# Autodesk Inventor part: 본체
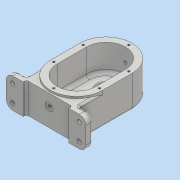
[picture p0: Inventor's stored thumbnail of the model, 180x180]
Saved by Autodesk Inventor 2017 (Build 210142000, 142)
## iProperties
Part Number: 본체
Material: 일반
Document SubType Name: Modeling
Designer: MRC
Density: 1 g/cm^3
Appearance: 기본값
Author: MRC
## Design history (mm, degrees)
sketch "스케치1"
  geometry: L1 (0, 0)-(0, -87); L2 (-40, 0)-(-40, -82); L3 (40, -82)-(40, 0); L4 (-40, -82)-(-61, -82); L5 (-61, -82)-(-61, -92); L6 (-61, -92)-(-35, -92); L7 (-35, -92)-(-35, -87); L8 (-35, -87)-(35, -87); L9 (35, -87)-(35, -92); L10 (35, -92)-(61, -92); L11 (61, -92)-(61, -82); L12 (61, -82)-(40, -82); A1 r 40 centre (0, 0) between (40, 0) and (-40, 0); 1 further point
  constraints: 26 end point, 4 parallel, 4 vertical, 2 collinear, 2 horizontal, 2 midpoint, 2 perpendicular, 2 point on circle, 2 tangent, 1 centre point
  dimensions: "d15" = 40 radius of A1; "d16" = 10 distance of L10.end L11.end; "d17" = 92 distance from line of L10 L1.start; "d18" = 70 distance of L7.end L8.end; "d19" = 122 distance between parallel lines of L11 L5; "d20" = 5 distance between parallel lines of L6 L8; "d21" = 61 distance from line of point (0, -43.5) L5
extrude "돌출1" new body sketch "스케치1" distance "d22" = 46; taper "d23" = 0 deg
sketch "스케치2"
  geometry: L1 (0, 0)-(0, -45); L2 (-40, 0)-(-40, -45); L3 (40, -45)-(40, 0); A1 r 40 centre (0, 0) between (40, 0) and (-40, 0) reference; A2 r 40 centre (0, 0) between (40, 0) and (-40, 0); A3 r 40 centre (0, -45) between (-40, -45) and (40, -45); 1 further point
  constraints: 8 end point, 4 point on circle, 4 tangent, 2 centre point, 1 concentric, 1 midpoint, 1 parallel, 1 vertical
  dimensions: "d24" = 45 distance of L1.end L1.start
extrude "돌출2" join sketch "스케치2" distance "d25" = 3; taper "d26" = 0 deg
sketch "스케치3"
  geometry: L1 (0, 0)-(0, -45); L2 (-26, 0)-(-26, -45); L3 (26, -45)-(26, 0); A1 r 40 centre (0, 0) between (40, 0) and (-40, 0) reference; A2 r 26 centre (0, 0) between (26, 0) and (-26, 0); A3 r 26 centre (0, -45) between (-26, -45) and (26, -45); 1 further point
  constraints: 8 end point, 4 point on circle, 4 tangent, 2 centre point, 1 midpoint, 1 parallel, 1 vertical
  dimensions: "d27" = 26 radius of A2; "d28" = 45 distance of L1.start L1.end
extrude "돌출3" join sketch "스케치3" distance "d29" = 11; taper "d30" = 0 deg
sketch "스케치4"
  geometry: L1 (-26, 0)-(-26, -45) reference; L2 (26, -45)-(26, 0) reference; L3 (-26, -45)-(-26, 0) reference; L4 (-26, -30)-(26, -30); A1 r 26 centre (0, 0) between (26, 0) and (-26, 0) reference
  constraints: 2 end point, 2 point on line, 1 perpendicular
  dimensions: "d31" = 30 distance from line of A1.centre L4
extrude "돌출4" cut sketch "스케치4" distance "d32" = 3; taper "d33" = 0 deg
sketch "스케치5"
  geometry: L1 (0, 0)-(0, -45); L2 (-30, 0)-(-30, -45); L3 (30, -45)-(30, 0); A1 r 40 centre (0, -45) between (-40, -45) and (40, -45) reference; A2 r 40 centre (0, 0) between (40, 0) and (-40, 0) reference; A3 r 30 centre (0, 0) between (30, 0) and (-30, 0); A4 r 30 centre (0, -45) between (-30, -45) and (30, -45); 1 further point
  constraints: 8 end point, 4 point on circle, 4 tangent, 2 centre point, 1 midpoint, 1 parallel, 1 vertical
  dimensions: "d34" = 30 radius of A3
extrude "돌출5" cut sketch "스케치5" distance "d35" = 41; taper "d36" = 0 deg
hole "구멍1" diameter "d39" = 20; stored, may be unused: countersink angle "d43" = 90 deg, drill point angle "d45" = 0 deg; dims "d40" = 6, "d41" = 28, "d42" = 8, "d44" = 12, "d46" = 10, "d47" = 10
hole "구멍2" diameter "d50" = 22; stored, may be unused: countersink angle "d54" = 90 deg, drill point angle "d56" = 0 deg; dims "d48" = 10, "d49" = 10, "d51" = 6, "d52" = 28, "d53" = 8, "d55" = 100
sketch "스케치6"
  geometry: C1 r 11 at (0, 0) reference; C2 r 14 at (0, 0); A1 r 26 centre (0, 0) between (26, 0) and (-26, 0) reference
  constraints: 1 centre point, 1 coincident
  dimensions: "d57" = 28 diameter of C2
extrude "돌출6" cut sketch "스케치6" distance "d58" = 4; taper "d59" = 0 deg
sketch "스케치8"
  geometry: L1 (0, 0)-(0, -45); L2 (35, 0)-(35, -45); L3 (-35, -45)-(-35, 0); A1 r 40 centre (0, -45) between (-40, -45) and (40, -45) reference; A2 r 40 centre (0, 0) between (40, 0) and (-40, 0) reference; A3 r 35 centre (0, 0) between (35, 0) and (-35, 0); A4 r 35 centre (0, -45) between (-35, -45) and (35, -45); 7 further points
  constraints: 8 end point, 6 point on circle, 4 coincident, 4 tangent, 2 centre point, 1 midpoint, 1 parallel, 1 vertical
  dimensions: "d60" = 35 radius of A3
hole "구멍3" sketch "스케치8" at (0, 35), (-35, 0), (35, 0), (35, -45), (-35, -45), (0, -80) diameter "d61" = 3.242; stored, may be unused: countersink angle "d65" = 90 deg, drill point angle "d67" = 118 deg; dims "d62" = 8, "d63" = 28, "d64" = 8, "d66" = 10
node "작업 평면1"
sketch "스케치9"
  geometry: C1 r 6 at (0, 28); 1 further point
  constraints: 1 centre point
  dimensions: "d69" = 12 diameter of C1; "d70" = 28 distance of C1.centre point (0, 0)
extrude "돌출7" join sketch "스케치9" stored distance "d71" = 4; taper "d72" = 0 deg
sketch "스케치10"
  geometry: C1 r 6 at (0, 0) reference; 2 further points
  constraints: 1 coincident
hole "구멍4" sketch "스케치10" at (0, 0) diameter "d73" = 4.917; stored, may be unused: countersink angle "d77" = 90 deg, drill point angle "d79" = 0 deg; dims "d74" = 12, "d75" = 28, "d76" = 8, "d78" = 17.1
sketch "스케치12"
  geometry: L1 (0, 0)-(70, 0) reference; L2 (75, 49)-(-5, 49) reference; 3 further points
  constraints: 1 midpoint, 1 vertical alignment
  dimensions: "d88" = 21 distance from line of point (35, 28) L2
hole "구멍5" sketch "스케치12" at (35, 28) diameter "d81" = 4.917; stored, may be unused: countersink angle "d85" = 90 deg, drill point angle "d87" = 0 deg; dims "d82" = 12, "d83" = 12, "d84" = 1, "d86" = 17.1
fillet "모깎기1" dims "d89" = 10
hole "구멍6" diameter "d92" = 6.6; stored, may be unused: countersink angle "d96" = 90 deg, drill point angle "d98" = 0 deg; dims "d90" = 10, "d91" = 10, "d93" = 12, "d94" = 11, "d95" = 2, "d97" = 17.1
hole "구멍7" diameter "d101" = 6.6; stored, may be unused: countersink angle "d105" = 90 deg, drill point angle "d107" = 0 deg; dims "d99" = 10, "d100" = 10, "d102" = 12, "d103" = 11, "d104" = 2, "d106" = 17.1
hole "구멍8" diameter "d110" = 6.6; stored, may be unused: countersink angle "d114" = 90 deg, drill point angle "d116" = 0 deg; dims "d108" = 10, "d109" = 10, "d111" = 12, "d112" = 11, "d113" = 2, "d115" = 17.1
hole "구멍9" diameter "d119" = 6.6; stored, may be unused: countersink angle "d123" = 90 deg, drill point angle "d125" = 0 deg; dims "d117" = 10, "d118" = 10, "d120" = 12, "d121" = 11, "d122" = 2, "d124" = 17.1
fillet "모깎기3" dims "d130" = 3
fillet "모깎기2" dims "d126" = 3
chamfer "모따기1" distance "d127" = 1; stored, may be unused: second distance "d128" = 2, angle "d129" = 45 deg
fillet "모깎기4" dims "d131" = 3
fillet "모깎기5" dims "d132" = 0.3
chamfer "모따기2" distance "d133" = 1; stored, may be unused: second distance "d134" = 2, angle "d135" = 45 deg
fillet "모깎기6" dims "d136" = 3
fillet "모깎기7" dims "d137" = 3
sketch "스케치13"
  geometry: L1 (-51, -92)-(-61, -92) reference; 1 further point
  constraints: 1 other
  dimensions: "d138" = 12 distance from line of L1 point (-0.116, -80)
feature "엠보싱1" sketch "스케치13" dims "d15" = 40, "d16" = 10, "d17" = 92, "d18" = 70, "d19" = 122, "d20" = 5, "d21" = 61, "d24" = 45, "d139" = 0.5, "d140" = 0
sketch "스케치14"
  geometry: A1 r 26 centre (0, 0) between (26, 0) and (-26, 0) reference; 1 further point
  constraints: 1 vertical alignment
  dimensions: "d141" = 20 distance of point (0, 20) A1.centre
hole "구멍10" sketch "스케치14" at (0, 20) diameter "d142" = 3.242; stored, may be unused: countersink angle "d146" = 90 deg, drill point angle "d148" = 118 deg; dims "d143" = 8, "d144" = 11, "d145" = 2, "d147" = 10
fillet "모깎기8" dims "d152" = 5
node "솔리드1"
pattern_circular "원형 패턴1" dims angle "d150" = 360 deg
other parameters: "d68" = 43
